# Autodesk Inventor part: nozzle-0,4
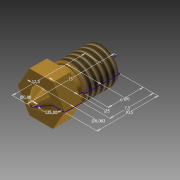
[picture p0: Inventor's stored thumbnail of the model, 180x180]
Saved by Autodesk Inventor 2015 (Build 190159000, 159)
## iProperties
Created: 2015-02
Part Number: nozzle-0,4
Material: Типовые
Document SubType Name: Modeling
Designer: Parabolik
Density: 1 g/cm^3
Appearance: Латунь - сатинированная
Author: Parabolik
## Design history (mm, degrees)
sketch "Эскиз1"
  geometry: L1 (0, 0)-(0, 15); L2 (0, 12.5)-(3, 12.5); L3 (1.84, 2)-(4.042, 2); L4 (2.5, 5)-(4.042, 5); L5 (2.5, 6.5)-(3, 6.5); L6 (0, 0)-(0.44, 0); L7 (2.5, 6.5)-(2.5, 5); L8 (3, 12.5)-(3, 6.5); L9 (0.44, 0)-(1.84, 2); L10 (4.042, 5)-(4.042, 2); L11 (0, 12.5)-(0, 0)
  constraints: 22 end point, 4 horizontal, 3 perpendicular, 1 collinear, 1 point on line, 1 vertical
  dimensions: "d0" = 15 distance of L1.start L1.end; "d1" = 12.5 distance from line of L1.start L2; "d2" = 10.5 distance between parallel lines of L3 L2; "d3" = 7.5 distance between parallel lines of L4 L2; "d4" = 6 distance between parallel lines of L5 L2; "d6" = 5 diameter of L7 L1; "d7" = 6 diameter of L8 L1; "d8" = 125 deg angle of L9 L3; "d11" = 8.083 diameter of L10 L1; "d44" = 0.88 diameter of L6.end L1
revolve "Вращение1" stored, may be unused: angle "d12" = 90 deg
chamfer "Фаска1" distance "d13" = 0.25; stored, may be unused: second distance "d14" = 2, angle "d15" = 45 deg
feature "Резьба1" dims "d37" = 10, "d38" = 0
sketch "Эскиз2"
  geometry: 2 further points
  constraints: 1 coincident
sketch "Эскиз3"
  geometry: 2 further points
  constraints: 1 coincident
hole "Отверстие1" sketch "Эскиз2" diameter "d16" = 1.5; stored, may be unused: countersink angle "d20" = 90 deg, drill point angle "d22" = 130 deg; dims "d17" = 6, "d18" = 4, "d19" = 2, "d21" = 11.7
hole "Отверстие2" sketch "Эскиз2" diameter "d23" = 2; stored, may be unused: countersink angle "d27" = 90 deg, drill point angle "d29" = 130 deg; dims "d24" = 6, "d25" = 4, "d26" = 2, "d28" = 10.5
chamfer "Фаска2" distance "d41" = 0.2; stored, may be unused: second distance "d42" = 2, angle "d43" = 45 deg
hole "Отверстие3" sketch "Эскиз3" diameter "d30" = 0.4; stored, may be unused: countersink angle "d34" = 90 deg, drill point angle "d36" = 0 deg; dims "d31" = 6, "d32" = 4, "d33" = 2, "d35" = 0.8
sketch "Эскиз4"
  geometry: L1 (4.042, 0)-(2.021, -3.5); L2 (2.021, -3.5)-(-2.021, -3.5); L3 (-2.021, -3.5)-(-4.042, 0); L4 (-4.042, 0)-(-2.021, 3.5); L5 (-2.021, 3.5)-(2.021, 3.5); L6 (2.021, 3.5)-(4.042, 0); C1 r 0.2 at (0, 0) reference; 3 further points
  constraints: 12 end point, 1 coincident, 1 horizontal alignment, 14 other
extrude "Выдавливание1" cut sketch "Эскиз4" distance "d39" = 3; taper "d40" = 0 deg
node "Твердое тело1"
